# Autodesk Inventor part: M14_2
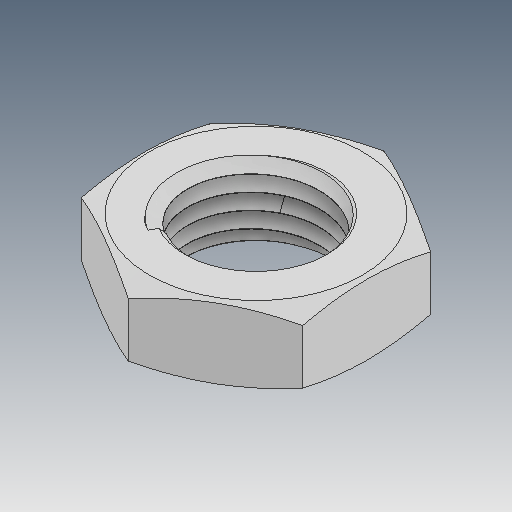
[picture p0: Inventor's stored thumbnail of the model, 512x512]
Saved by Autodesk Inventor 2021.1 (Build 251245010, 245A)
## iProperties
Created: 2019-05
Part Number: M14_2
Material: Ogólny
Document SubType Name: Modeling
Designer: user
Density: 1 g/cm^3
Appearance: Domyślna
Author: user
Revision Number: ÈÎºÎ
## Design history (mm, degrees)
feature "ÊäÈë1"
node "Bryła1"
